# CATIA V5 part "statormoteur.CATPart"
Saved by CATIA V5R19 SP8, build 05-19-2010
Part number: statormoteur
Revision: ANY
Definition: UNKNOWN
Nomenclature: statormoteur
Source: Unknown
Bounding box of the stored display mesh (mm): x -5.491 to 5.5, y -19.8 to 0, z -5.5 to 5.5
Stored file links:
  D:\Documents\1_Travail\1 - ac-limoges.fr\ac-limoges.fr\Emmanuel Maynard - STI2D_Turgot\2 -2I2D\2_SEQUENCE_Serrure_Biométrique\5-Spé_ITEC\Serrure_Bio_Eleve\statormoteur.CATPart
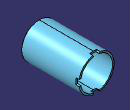
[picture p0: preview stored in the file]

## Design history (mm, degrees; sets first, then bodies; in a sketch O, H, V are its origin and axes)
Body1 "Répétition circulaire1" (main body)
  Solid1: solid without history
